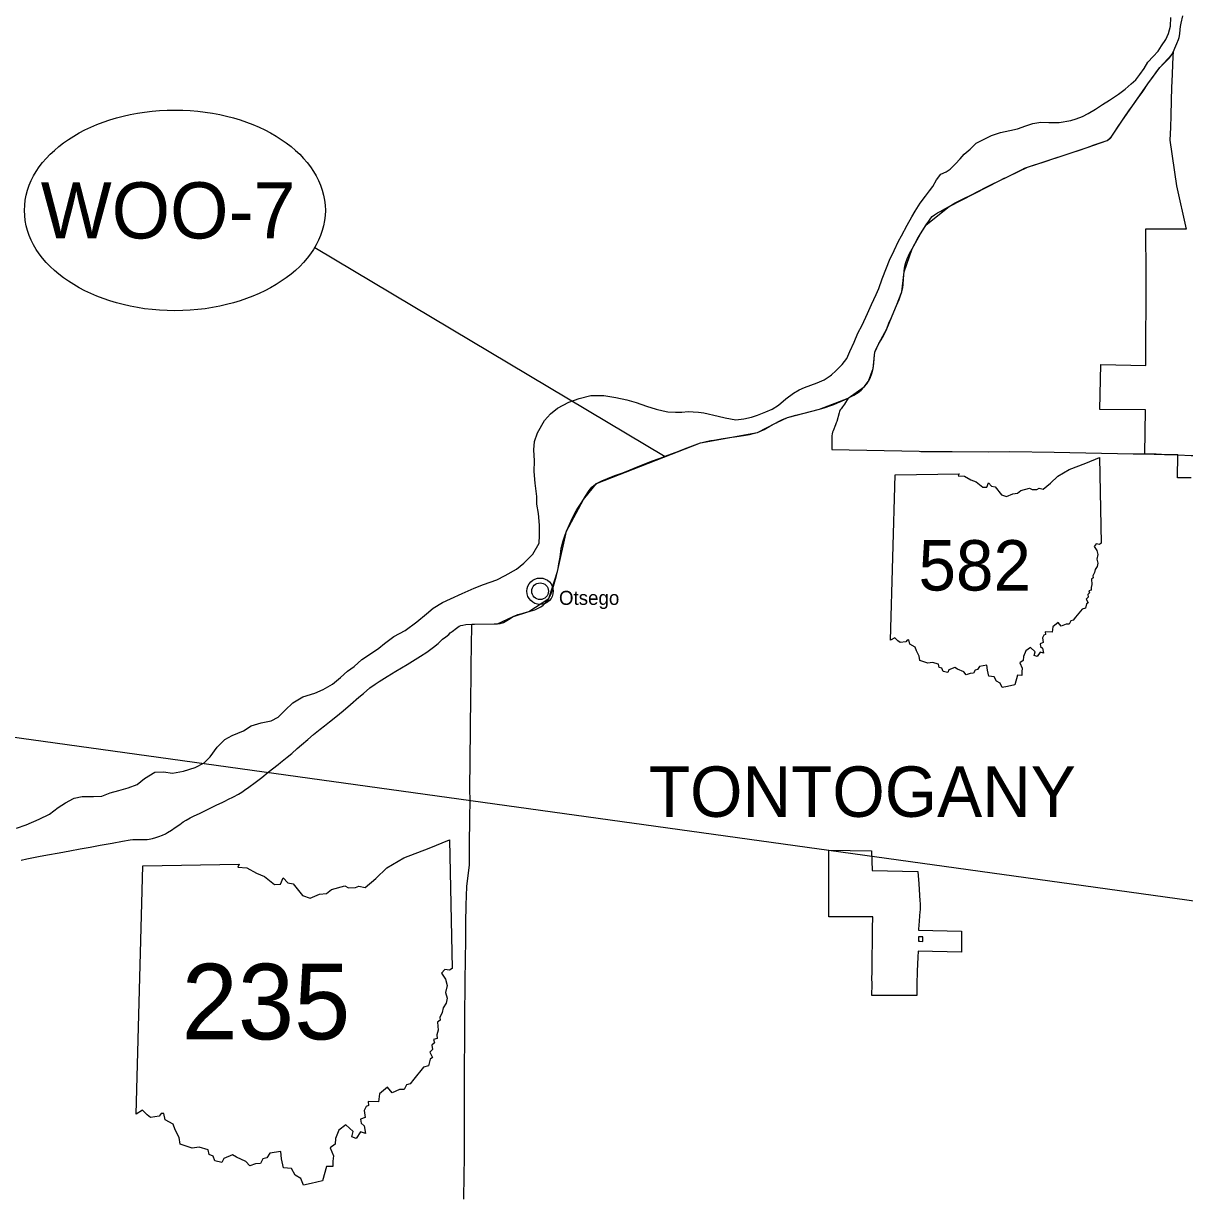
# Model space of a CAD drawing. Extents: x 0 to 851, y 0 to 440.
# Drawn here: x 229.7 to 287.6, y 226.5 to 285 of the extents above; entities that cross this region are included whole.
import ezdxf

# ---------------------------------------------------------------- set-up
doc = ezdxf.new("R2010")
doc.units = 0
for name, color, linetype in [('DV_X_Corp_Line', 7, 'Continuous'), ('GM_X_Corporation_Text', 7, 'Continuous'), ('GM_X_County', 7, 'Continuous'), ('GM_X_State_Route', 7, 'Continuous'), ('PV_P_Text', 7, 'Continuous'), ('RD_P_Fence', 7, 'Continuous'), ('SH_Data', 7, 'Continuous')]:
    doc.layers.add(name, color=color, linetype=linetype)

msp = doc.modelspace()

# ---------------------------------------------------------------- linework, layer by layer
at = {"layer": 'DV_X_Corp_Line'}
msp.add_lwpolyline([(287.89, 262.358), (287.214, 262.364), (287.226, 263.508), (286.959, 263.514), (286.412, 263.531), (286.15, 263.539), (285.583, 263.552), (285.61, 265.754), (283.346, 265.779), (283.384, 268.019), (285.636, 267.96), (285.647, 272.445), (285.628, 274.777), (287.638, 274.782)], dxfattribs=at)
for points in [[(272.021, 240.489), (269.829, 240.485), (269.831, 241.615), (269.828, 243.804), (271.964, 243.782), (271.987, 242.792), (274.268, 242.751), (274.319, 242.128), (274.369, 241.281), (274.378, 241.148), (274.381, 241.05), (274.377, 240.82), (274.374, 240.748), (274.317, 240.053), (274.309, 239.884), (274.306, 239.815), (276.448, 239.77), (276.443, 238.733), (274.278, 238.78), (274.267, 238.484), (274.24, 237.785), (274.217, 237.121), (274.214, 236.575), (271.978, 236.573), (271.992, 237.134), (271.984, 237.244), (271.981, 237.336), (271.983, 237.818), (271.993, 238.505), (272.008, 239.209), (272.012, 239.913)], [(274.294, 239.268), (274.361, 239.267), (274.51, 239.264), (274.514, 239.485), (274.357, 239.488), (274.298, 239.489)]]:
    msp.add_lwpolyline(points, close=True, dxfattribs=at)
for radius in [0.658, 0.417]:
    msp.add_circle((255.436, 256.715), radius, dxfattribs=at)
at = {"layer": 'GM_X_County'}
msp.add_lwpolyline([(229.341, 244.9), (229.822, 245.07), (230.466, 245.348), (230.989, 245.597), (231.418, 245.929), (231.779, 246.171), (232.178, 246.388), (232.211, 246.406), (232.616, 246.489), (233.172, 246.48), (233.593, 246.499), (234.006, 246.67), (234.439, 246.787), (234.91, 246.923), (235.357, 247.083), (235.715, 247.386), (236.225, 247.696), (236.667, 247.712), (237.113, 247.647), (237.657, 247.755), (238.249, 247.929), (238.691, 248.164), (238.989, 248.461), (239.344, 248.946), (239.72, 249.322), (240.087, 249.525), (240.647, 249.764), (241.031, 250.006), (241.532, 250.158), (242.029, 250.261), (242.382, 250.446), (242.728, 250.783), (243.111, 251.156), (243.614, 251.447), (244.2, 251.642), (244.631, 251.823), (245.093, 252.077), (245.482, 252.42), (245.844, 252.733), (246.161, 252.96), (246.548, 253.317), (246.935, 253.555), (247.392, 253.874), (247.682, 254.108), (248.139, 254.456), (248.706, 254.763), (249.296, 255.186), (249.777, 255.582), (250.099, 255.869), (250.568, 256.147), (250.975, 256.338), (251.559, 256.604), (252.155, 256.866), (252.617, 257.054), (253.277, 257.291), (253.691, 257.5), (254.255, 257.813), (254.619, 258.111), (254.662, 258.146), (255.069, 258.569), (255.385, 259.102), (255.411, 259.485), (255.413, 260.007), (255.352, 260.593), (255.279, 261.052), (255.269, 261.433), (255.196, 262.1), (255.148, 262.686), (255.154, 263.208), (255.119, 263.764), (255.163, 264.17), (255.312, 264.615), (255.652, 265.225), (255.957, 265.55), (256.309, 265.843), (256.869, 266.13), (257.377, 266.32), (257.962, 266.465), (258.616, 266.47), (259.21, 266.373), (259.753, 266.259), (260.233, 266.123), (260.748, 265.936), (261.217, 265.787), (261.572, 265.7), (261.804, 265.649), (262.191, 265.639), (262.507, 265.647), (262.811, 265.666), (263.076, 265.658), (263.342, 265.643), (263.597, 265.599), (263.822, 265.548), (264.101, 265.496), (264.315, 265.442), (264.657, 265.362), (265.194, 265.262), (265.586, 265.309), (265.971, 265.39), (266.279, 265.496), (266.689, 265.657), (267.001, 265.787), (267.314, 265.99), (267.693, 266.31), (268.068, 266.583), (268.354, 266.746), (268.612, 266.873), (269.257, 267.101), (269.597, 267.255), (269.893, 267.442), (269.963, 267.503), (270.182, 267.693), (270.497, 268.014), (270.724, 268.312), (270.871, 268.67), (271.087, 269.134), (271.279, 269.574), (271.488, 269.978), (271.753, 270.555), (271.952, 270.999), (272.189, 271.506), (272.325, 271.8), (272.498, 272.284), (272.702, 272.836), (272.86, 273.22), (273.093, 273.697), (273.306, 274.157), (273.461, 274.424), (273.739, 274.967), (273.968, 275.381), (274.131, 275.66), (274.389, 276.053), (274.647, 276.398), (274.853, 276.671), (275.018, 276.893), (275.195, 277.216), (275.408, 277.505), (275.675, 277.618), (275.886, 277.756), (276.152, 278.011), (276.379, 278.269), (276.581, 278.498), (276.881, 278.748), (277.178, 279.049), (277.51, 279.219), (277.934, 279.433), (278.386, 279.577), (278.861, 279.67), (279.232, 279.755), (279.658, 279.902), (279.996, 280.028), (280.397, 280.088), (280.793, 280.071), (281.314, 280.073), (281.9, 280.177), (282.16, 280.25), (282.471, 280.369), (282.762, 280.522), (283.129, 280.748), (283.476, 280.974), (283.819, 281.191), (284.267, 281.492), (284.607, 281.729), (284.897, 281.996), (285.132, 282.208), (285.342, 282.473), (285.552, 282.759), (285.732, 283.079), (286.005, 283.363), (286.255, 283.628), (286.418, 283.894), (286.635, 284.21), (286.764, 284.514), (286.857, 284.869), (286.885, 285.309)], dxfattribs=at)
at = {"layer": 'GM_X_State_Route'}
for points in [[(287.006, 283.612), (287.04, 283.689), (287.08, 283.782), (287.177, 284.009), (287.268, 284.216), (287.3, 284.319), (287.326, 284.5), (287.343, 284.715), (287.362, 284.852), (287.395, 285.02), (287.473, 285.386)], [(270.798, 266.334), (270.941, 266.415), (271.076, 266.493), (271.298, 266.625), (271.447, 266.738), (271.588, 266.906), (271.718, 267.055), (271.814, 267.181), (271.887, 267.331), (271.971, 267.558), (272.039, 267.809), (272.067, 268.067), (272.084, 268.308), (272.104, 268.5), (272.123, 268.623), (272.179, 268.77), (272.259, 268.924), (272.321, 269.06), (272.438, 269.246), (272.562, 269.442), (272.639, 269.609), (272.716, 269.786), (272.828, 270.076), (272.956, 270.363), (273.065, 270.647), (273.204, 270.96), (273.33, 271.25), (273.41, 271.447), (273.474, 271.634), (273.517, 271.828), (273.541, 272.023), (273.561, 272.264), (273.578, 272.465), (273.586, 272.639), (273.589, 272.684), (273.6, 272.794), (273.623, 272.921), (273.676, 273.099), (273.736, 273.282), (273.858, 273.542), (273.979, 273.775), (274.114, 274.025), (274.249, 274.275), (274.394, 274.528), (274.545, 274.757), (274.689, 274.976), (274.817, 275.165), (274.913, 275.302), (274.988, 275.394), (275.093, 275.48), (275.249, 275.568), (275.418, 275.659), (275.608, 275.767), (275.834, 275.888), (276.129, 276.064), (276.49, 276.256), (276.94, 276.474), (277.298, 276.653), (277.67, 276.845), (277.981, 276.997), (278.319, 277.166), (278.575, 277.293), (278.667, 277.339), (278.971, 277.485), (279.241, 277.618), (279.468, 277.738), (279.586, 277.794), (279.731, 277.845), (280.152, 277.989), (280.621, 278.139), (281.093, 278.299), (281.517, 278.433), (281.968, 278.573), (282.319, 278.695), (282.717, 278.823), (283.064, 278.958), (283.449, 279.1), (283.698, 279.186), (283.769, 279.222), (283.84, 279.265), (283.912, 279.344), (284.046, 279.547), (284.259, 279.869), (284.445, 280.141), (284.644, 280.44), (284.726, 280.551), (284.826, 280.706), (285.022, 280.978), (285.258, 281.307), (285.478, 281.625), (285.739, 281.997), (286.014, 282.386), (286.223, 282.674), (286.326, 282.814), (286.445, 282.926), (286.667, 283.154), (286.803, 283.286), (286.868, 283.359), (286.937, 283.469), (287.006, 283.612)], [(286.992, 283.342), (286.992, 283.357), (287.006, 283.612)], [(287.654, 274.76), (287.187, 276.916), (286.85, 279.198), (286.876, 279.819), (286.892, 280.43), (286.918, 281.178), (286.936, 281.82), (286.964, 282.464), (286.986, 282.978), (286.992, 283.339), (286.992, 283.342)], [(256.358, 257.978), (256.384, 258.16), (256.435, 258.414), (256.471, 258.692), (256.496, 258.864), (256.536, 259.023), (256.573, 259.176), (256.651, 259.421), (256.754, 259.716), (256.903, 260.042), (257.067, 260.401), (257.243, 260.718), (257.357, 260.903), (257.479, 261.101), (257.6, 261.279), (257.697, 261.447), (257.845, 261.684), (257.937, 261.809), (258.018, 261.894), (258.118, 261.989), (258.254, 262.089), (258.352, 262.14), (258.518, 262.215), (258.799, 262.327), (259.171, 262.479), (259.518, 262.604), (259.928, 262.769), (260.328, 262.927), (260.997, 263.191), (261.415, 263.344), (261.808, 263.495), (262.227, 263.649), (262.629, 263.808), (263.163, 264.017), (263.433, 264.106), (263.577, 264.143), (263.722, 264.175), (263.954, 264.222), (264.103, 264.247), (264.465, 264.316), (264.876, 264.376), (265.239, 264.429), (265.575, 264.477), (265.876, 264.529), (266.125, 264.589), (266.271, 264.63), (266.431, 264.685), (266.606, 264.783), (266.882, 264.94), (267.205, 265.11), (267.29, 265.155), (267.526, 265.274), (267.767, 265.367), (268.188, 265.483), (268.674, 265.607), (268.988, 265.692), (269.365, 265.796), (269.654, 265.877), (269.873, 265.947), (269.937, 265.969), (270.078, 266.017), (270.268, 266.105), (270.46, 266.182), (270.798, 266.334)], [(270.798, 266.334), (270.615, 266.036), (270.518, 265.907), (270.448, 265.813), (270.401, 265.75), (270.367, 265.672), (270.339, 265.607), (270.233, 265.178), (270.204, 265.1), (270.164, 265), (270.049, 264.714), (270.02, 264.643), (269.997, 264.564), (269.984, 264.466), (269.973, 263.775), (274.33, 263.687)], [(274.33, 263.687), (274.417, 263.685), (275.985, 263.676), (277.766, 263.67), (278.848, 263.674), (281.069, 263.64), (285, 263.568), (285.541, 263.556)], [(285.541, 263.556), (286.568, 263.535), (287.241, 263.51)], [(287.241, 263.51), (287.893, 263.485), (288.045, 263.479)], [(254.636, 255.639), (254.708, 255.657), (254.881, 255.7), (255.051, 255.761), (255.176, 255.794), (255.482, 255.934), (255.59, 256.017), (255.708, 256.129), (255.817, 256.269), (255.871, 256.353), (255.963, 256.524), (256.024, 256.688), (256.139, 257.086), (256.206, 257.312), (256.257, 257.497), (256.298, 257.697), (256.339, 257.85), (256.358, 257.978)], [(252.033, 255.074), (252.166, 255.077), (253.155, 255.082), (253.312, 255.086), (253.453, 255.106), (253.606, 255.161), (253.777, 255.256), (253.939, 255.359), (254.061, 255.434), (254.133, 255.471), (254.254, 255.53), (254.325, 255.552), (254.458, 255.594), (254.59, 255.628), (254.636, 255.639)], [(229.575, 243.319), (229.852, 243.38), (230.429, 243.489), (230.884, 243.569), (231.463, 243.677), (232.001, 243.778), (232.507, 243.872), (233.001, 243.963), (233.503, 244.054), (234.102, 244.163), (234.62, 244.26), (234.999, 244.326), (235.133, 244.338), (235.243, 244.343), (235.432, 244.343), (235.711, 244.345), (235.843, 244.348), (235.957, 244.359), (236.12, 244.393), (236.287, 244.434), (236.436, 244.485), (236.621, 244.562), (236.757, 244.623), (236.862, 244.685), (237.059, 244.809), (237.251, 244.944), (237.471, 245.094), (237.644, 245.215), (237.79, 245.3), (237.99, 245.42), (238.195, 245.52), (238.464, 245.642), (238.756, 245.78), (239.059, 245.934), (239.32, 246.065), (239.582, 246.193), (239.754, 246.275), (239.869, 246.33), (240.15, 246.469), (240.405, 246.608), (240.567, 246.702), (240.704, 246.8), (240.918, 246.955), (241.24, 247.188), (241.558, 247.433), (241.888, 247.695), (242.375, 248.081), (242.503, 248.173), (242.832, 248.443), (243.061, 248.621), (243.328, 248.875), (243.542, 249.055), (243.857, 249.317), (244.14, 249.569), (244.477, 249.834), (244.698, 250.004), (244.938, 250.202), (245.251, 250.449), (245.627, 250.752), (245.985, 251.071), (246.406, 251.429), (246.634, 251.621), (246.953, 251.895), (247.208, 252.084), (247.41, 252.208), (247.816, 252.46), (248.249, 252.728), (248.808, 253.065), (249.478, 253.476), (249.788, 253.681), (250.116, 253.921), (250.356, 254.114), (250.573, 254.321), (250.734, 254.436), (250.885, 254.565), (250.957, 254.64), (251.056, 254.712), (251.269, 254.872), (251.402, 254.966), (251.493, 255.004), (251.583, 255.03), (251.729, 255.057), (252.033, 255.074)], [(251.638, 226.413), (251.65, 227.606), (251.664, 228.47), (251.666, 229.377), (251.67, 230.342), (251.665, 231.256), (251.668, 232.362), (251.672, 232.864), (251.674, 233.152), (251.683, 234.207), (251.69, 235.169), (251.692, 235.942), (251.694, 236.725), (251.705, 237.32), (251.716, 238.345), (251.731, 239.346), (251.741, 240.186), (251.759, 241.07), (251.778, 241.991), (251.91, 243.072), (251.924, 244.007), (251.933, 245.454), (251.946, 246.256), (251.941, 246.879), (251.946, 248.255), (251.992, 251.474), (251.994, 252.372), (251.997, 253.081), (252.015, 253.945), (252.033, 255.074)]]:
    msp.add_lwpolyline(points, dxfattribs=at)
at = {"layer": 'PV_P_Text'}
for p, q in [((272.904, 254.268), (273.134, 262.516)), ((272.904, 254.268), (273.134, 262.516)), ((235.294, 230.659), (235.64, 243.031)), ((235.294, 230.659), (235.64, 243.031))]:
    msp.add_line(p, q, dxfattribs=at)
for points in [[(273.134, 262.516), (276.335, 262.57), (276.285, 262.47), (276.587, 262.449), (276.908, 262.273), (277.179, 262.162), (277.511, 261.899), (277.709, 261.902), (277.793, 262.117), (277.945, 261.952), (278.126, 261.922), (278.438, 261.527), (278.695, 261.442), (279.004, 261.577), (279.234, 261.599), (279.403, 261.733), (279.842, 261.847), (279.964, 261.779), (280.197, 261.793), (280.314, 261.843), (280.517, 261.798), (280.874, 262.098), (281.241, 262.451), (281.806, 262.785), (282.651, 263.101), (283.318, 263.384), (283.415, 259.104)], [(273.134, 262.516), (276.335, 262.57), (276.285, 262.47), (276.587, 262.449), (276.908, 262.273), (277.179, 262.162), (277.511, 261.899), (277.709, 261.902), (277.793, 262.117), (277.945, 261.952), (278.126, 261.922), (278.438, 261.527), (278.695, 261.442), (279.004, 261.577), (279.234, 261.599), (279.403, 261.733), (279.842, 261.847), (279.964, 261.779), (280.197, 261.793), (280.314, 261.843), (280.517, 261.798), (280.874, 262.098), (281.241, 262.451), (281.806, 262.785), (282.651, 263.101), (283.318, 263.384), (283.415, 259.104)], [(283.415, 259.104), (283.316, 259.044), (283.163, 259.072), (283.06, 258.952), (283.187, 258.751), (283.247, 258.54), (283.194, 258.307), (283.247, 258.114), (283.211, 257.953), (283.114, 257.793), (283.081, 257.64), (282.999, 257.479), (283.006, 257.389), (282.928, 257.318), (282.942, 257.05), (282.903, 256.902), (282.916, 256.774), (282.789, 256.74), (282.819, 256.634), (282.738, 256.553), (282.755, 256.412), (282.664, 256.323), (282.752, 256.143), (282.681, 256.086), (282.622, 255.868), (282.46, 255.823), (282.134, 255.424), (282.019, 255.273), (281.89, 255.235), (281.819, 255.08), (281.66, 255.08), (281.42, 254.972), (281.265, 255.157), (280.992, 254.934), (280.961, 254.677), (280.617, 254.685), (280.63, 254.555), (280.553, 254.517), (280.483, 254.387), (280.524, 254.156), (280.363, 254.097), (280.382, 253.962), (280.485, 253.88), (280.531, 253.623), (280.36, 253.675), (280.22, 253.459), (280.075, 253.51), (280.123, 253.693), (279.879, 253.914), (279.648, 253.737), (279.528, 253.455), (279.526, 253.265), (279.355, 253.15), (279.465, 252.882), (279.445, 252.697), (279.448, 252.522), (279.233, 252.528), (279.103, 252.054)], [(283.415, 259.104), (283.316, 259.044), (283.163, 259.072), (283.06, 258.952), (283.187, 258.751), (283.247, 258.54), (283.194, 258.307), (283.247, 258.114), (283.211, 257.953), (283.114, 257.793), (283.081, 257.64), (282.999, 257.479), (283.006, 257.389), (282.928, 257.318), (282.942, 257.05), (282.903, 256.902), (282.916, 256.774), (282.789, 256.74), (282.819, 256.634), (282.738, 256.553), (282.755, 256.412), (282.664, 256.323), (282.752, 256.143), (282.681, 256.086), (282.622, 255.868), (282.46, 255.823), (282.134, 255.424), (282.019, 255.273), (281.89, 255.235), (281.819, 255.08), (281.66, 255.08), (281.42, 254.972), (281.265, 255.157), (280.992, 254.934), (280.961, 254.677), (280.617, 254.685), (280.63, 254.555), (280.553, 254.517), (280.483, 254.387), (280.524, 254.156), (280.363, 254.097), (280.382, 253.962), (280.485, 253.88), (280.531, 253.623), (280.36, 253.675), (280.22, 253.459), (280.075, 253.51), (280.123, 253.693), (279.879, 253.914), (279.648, 253.737), (279.528, 253.455), (279.526, 253.265), (279.355, 253.15), (279.465, 252.882), (279.445, 252.697), (279.448, 252.522), (279.233, 252.528), (279.103, 252.054)], [(279.103, 252.054), (278.73, 251.964), (278.47, 251.91), (278.379, 252.125), (278.194, 252.238), (278.073, 252.455), (277.807, 252.484), (277.744, 252.782), (277.714, 253.023), (277.35, 252.963), (277.25, 252.816), (277.121, 252.776), (277.046, 252.628), (276.87, 252.615), (276.681, 252.545), (276.558, 252.691), (276.248, 252.837), (276.109, 252.913), (275.818, 252.795), (275.756, 252.657), (275.525, 252.718), (275.47, 252.873), (275.33, 252.919), (275.299, 253.083), (275, 253.171), (274.771, 253.136), (274.367, 253.268), (274.342, 253.484), (274.205, 253.748), (274.133, 253.931), (273.877, 254.07), (273.826, 254.288), (273.744, 254.281), (273.669, 254.193), (273.386, 254.153), (273.272, 254.242), (273.114, 254.393), (272.904, 254.268)], [(279.103, 252.054), (278.73, 251.964), (278.47, 251.91), (278.379, 252.125), (278.194, 252.238), (278.073, 252.455), (277.807, 252.484), (277.744, 252.782), (277.714, 253.023), (277.35, 252.963), (277.25, 252.816), (277.121, 252.776), (277.046, 252.628), (276.87, 252.615), (276.681, 252.545), (276.558, 252.691), (276.248, 252.837), (276.109, 252.913), (275.818, 252.795), (275.756, 252.657), (275.525, 252.718), (275.47, 252.873), (275.33, 252.919), (275.299, 253.083), (275, 253.171), (274.771, 253.136), (274.367, 253.268), (274.342, 253.484), (274.205, 253.748), (274.133, 253.931), (273.877, 254.07), (273.826, 254.288), (273.744, 254.281), (273.669, 254.193), (273.386, 254.153), (273.272, 254.242), (273.114, 254.393), (272.904, 254.268)], [(235.64, 243.031), (240.441, 243.112), (240.366, 242.962), (240.819, 242.931), (241.3, 242.666), (241.707, 242.5), (242.204, 242.106), (242.502, 242.111), (242.628, 242.433), (242.856, 242.184), (243.127, 242.14), (243.595, 241.547), (243.981, 241.419), (244.444, 241.622), (244.79, 241.656), (245.042, 241.856), (245.701, 242.028), (245.885, 241.925), (246.234, 241.946), (246.409, 242.022), (246.713, 241.954), (247.249, 242.404), (247.8, 242.934), (248.648, 243.435), (249.914, 243.909), (250.916, 244.333), (251.06, 237.912)], [(235.64, 243.031), (240.441, 243.112), (240.366, 242.962), (240.819, 242.931), (241.3, 242.666), (241.707, 242.5), (242.204, 242.106), (242.502, 242.111), (242.628, 242.433), (242.856, 242.184), (243.127, 242.14), (243.595, 241.547), (243.981, 241.419), (244.444, 241.622), (244.79, 241.656), (245.042, 241.856), (245.701, 242.028), (245.885, 241.925), (246.234, 241.946), (246.409, 242.022), (246.713, 241.954), (247.249, 242.404), (247.8, 242.934), (248.648, 243.435), (249.914, 243.909), (250.916, 244.333), (251.06, 237.912)], [(251.06, 237.912), (250.913, 237.822), (250.682, 237.865), (250.528, 237.684), (250.719, 237.384), (250.81, 237.067), (250.729, 236.717), (250.808, 236.428), (250.755, 236.187), (250.61, 235.946), (250.56, 235.717), (250.437, 235.476), (250.448, 235.341), (250.33, 235.234), (250.351, 234.832), (250.292, 234.609), (250.313, 234.417), (250.123, 234.367), (250.166, 234.209), (250.045, 234.086), (250.071, 233.875), (249.934, 233.741), (250.067, 233.471), (249.96, 233.386), (249.872, 233.058), (249.628, 232.992), (249.139, 232.393), (248.967, 232.166), (248.774, 232.11), (248.667, 231.877), (248.429, 231.876), (248.068, 231.715), (247.835, 231.993), (247.427, 231.659), (247.38, 231.273), (246.863, 231.285), (246.883, 231.09), (246.768, 231.033), (246.663, 230.838), (246.724, 230.491), (246.482, 230.402), (246.512, 230.2), (246.666, 230.077), (246.735, 229.692), (246.478, 229.77), (246.268, 229.445), (246.051, 229.521), (246.122, 229.797), (245.757, 230.127), (245.411, 229.862), (245.23, 229.439), (245.228, 229.154), (244.97, 228.982), (245.136, 228.58), (245.105, 228.303), (245.11, 228.039), (244.788, 228.049), (244.593, 227.338)], [(251.06, 237.912), (250.913, 237.822), (250.682, 237.865), (250.528, 237.684), (250.719, 237.384), (250.81, 237.067), (250.729, 236.717), (250.808, 236.428), (250.755, 236.187), (250.61, 235.946), (250.56, 235.717), (250.437, 235.476), (250.448, 235.341), (250.33, 235.234), (250.351, 234.832), (250.292, 234.609), (250.313, 234.417), (250.123, 234.367), (250.166, 234.209), (250.045, 234.086), (250.071, 233.875), (249.934, 233.741), (250.067, 233.471), (249.96, 233.386), (249.872, 233.058), (249.628, 232.992), (249.139, 232.393), (248.967, 232.166), (248.774, 232.11), (248.667, 231.877), (248.429, 231.876), (248.068, 231.715), (247.835, 231.993), (247.427, 231.659), (247.38, 231.273), (246.863, 231.285), (246.883, 231.09), (246.768, 231.033), (246.663, 230.838), (246.724, 230.491), (246.482, 230.402), (246.512, 230.2), (246.666, 230.077), (246.735, 229.692), (246.478, 229.77), (246.268, 229.445), (246.051, 229.521), (246.122, 229.797), (245.757, 230.127), (245.411, 229.862), (245.23, 229.439), (245.228, 229.154), (244.97, 228.982), (245.136, 228.58), (245.105, 228.303), (245.11, 228.039), (244.788, 228.049), (244.593, 227.338)], [(244.593, 227.338), (244.033, 227.203), (243.644, 227.121), (243.507, 227.444), (243.229, 227.614), (243.048, 227.939), (242.648, 227.983), (242.554, 228.429), (242.509, 228.791), (241.963, 228.702), (241.813, 228.481), (241.62, 228.421), (241.507, 228.198), (241.243, 228.18), (240.96, 228.074), (240.775, 228.293), (240.31, 228.513), (240.102, 228.626), (239.666, 228.45), (239.572, 228.242), (239.225, 228.334), (239.144, 228.566), (238.934, 228.636), (238.887, 228.882), (238.438, 229.013), (238.095, 228.961), (237.489, 229.159), (237.452, 229.484), (237.245, 229.879), (237.138, 230.153), (236.755, 230.363), (236.677, 230.689), (236.554, 230.679), (236.442, 230.547), (236.017, 230.486), (235.847, 230.619), (235.609, 230.847), (235.294, 230.659)], [(244.593, 227.338), (244.033, 227.203), (243.644, 227.121), (243.507, 227.444), (243.229, 227.614), (243.048, 227.939), (242.648, 227.983), (242.554, 228.429), (242.509, 228.791), (241.963, 228.702), (241.813, 228.481), (241.62, 228.421), (241.507, 228.198), (241.243, 228.18), (240.96, 228.074), (240.775, 228.293), (240.31, 228.513), (240.102, 228.626), (239.666, 228.45), (239.572, 228.242), (239.225, 228.334), (239.144, 228.566), (238.934, 228.636), (238.887, 228.882), (238.438, 229.013), (238.095, 228.961), (237.489, 229.159), (237.452, 229.484), (237.245, 229.879), (237.138, 230.153), (236.755, 230.363), (236.677, 230.689), (236.554, 230.679), (236.442, 230.547), (236.017, 230.486), (235.847, 230.619), (235.609, 230.847), (235.294, 230.659)]]:
    msp.add_lwpolyline(points, dxfattribs=at)
at = {"layer": 'RD_P_Fence'}
for points in [[(270.798, 266.334), (271.588, 266.906), (271.814, 267.181), (272.039, 267.809), (272.084, 268.308), (272.123, 268.623), (272.321, 269.06), (272.716, 269.786), (272.956, 270.363), (273.204, 270.96), (273.474, 271.634), (273.586, 272.639), (273.979, 273.775), (274.394, 274.528), (274.689, 274.976), (275.834, 275.888), (278.319, 277.166), (279.731, 277.845), (281.517, 278.433), (282.717, 278.823), (283.698, 279.186), (283.912, 279.344), (284.445, 280.141), (285.739, 281.997), (286.326, 282.814), (286.937, 283.469)], [(252.166, 255.077), (253.312, 255.086), (254.061, 255.434), (254.881, 255.7), (255.871, 256.353), (256.298, 257.697), (256.754, 259.716), (257.6, 261.279), (258.254, 262.089), (263.433, 264.106), (266.271, 264.63), (267.205, 265.11), (267.767, 265.367), (269.365, 265.796), (270.798, 266.334)]]:
    msp.add_lwpolyline(points, dxfattribs=at)
at = {"layer": 'SH_Data'}
for p, q in [((244.203, 273.848), (261.68, 263.424)), ((223.462, 250.235), (295.053, 240.313))]:
    msp.add_line(p, q, dxfattribs=at)
msp.add_ellipse((237.234, 275.695), major_axis=(7.5, 0), ratio=0.666667, dxfattribs=at)

# ---------------------------------------------------------------- texts
at = {"layer": 'DV_X_Corp_Line'}
msp.add_text('Otsego', height=0.6979, rotation=0.00001, dxfattribs=at).set_placement((256.377, 256.035))
at = {"layer": 'GM_X_Corporation_Text'}
msp.add_text('TONTOGANY', height=2.5126, rotation=0.00001, dxfattribs=at).set_placement((260.861, 245.471))
at = {"layer": 'PV_P_Text'}
for s, height, p in [('582', 2.5126, (274.3, 256.749)), ('235', 3.7688, (237.567, 234.38))]:
    msp.add_text(s, height=height, dxfattribs=at).set_placement(p)
at = {"layer": 'SH_Data'}
msp.add_text('WOO-7', height=2.8, dxfattribs=at).set_placement((230.546, 274.295))

doc.saveas('drawing.dxf')
